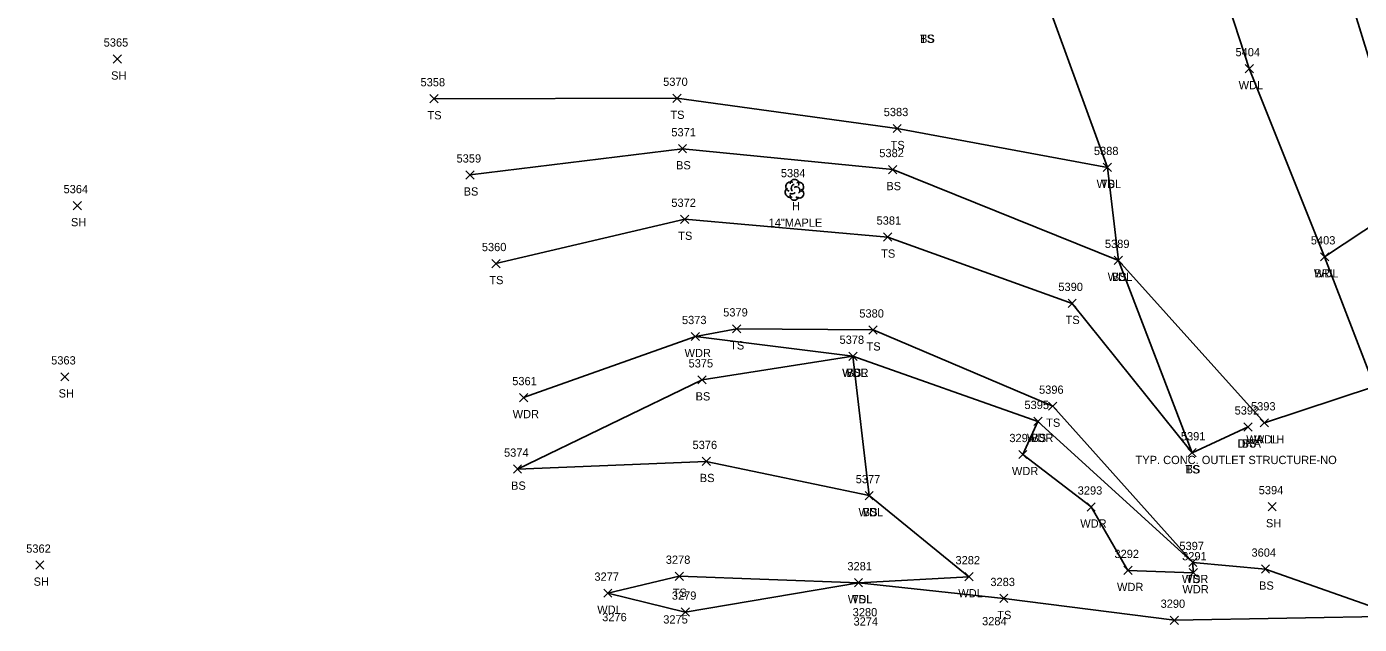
# Model space of a CAD drawing. Extents: x 1601151 to 1602912, y 499508 to 501770.
# Drawn here: x 1601159.4 to 1601482.2, y 500809.5 to 500954.3 of the extents above; entities that cross this region are included whole.
import ezdxf

# ---------------------------------------------------------------- set-up
doc = ezdxf.new("R2010")
doc.units = 0
for name, color, linetype in [('D_A', 7, 'Continuous'), ('D_C', 7, 'Continuous'), ('D_I', 7, 'Continuous'), ('D_TIC', 7, 'Continuous'), ('L_A', 7, 'Continuous'), ('L_C', 7, 'Continuous'), ('L_I', 7, 'Continuous'), ('L_TIC', 7, 'Continuous'), ('LABL', 7, 'Continuous'), ('LAWA', 7, 'Continuous'), ('LELB', 7, 'Continuous'), ('LTD', 7, 'Continuous'), ('UCO', 7, 'Continuous')]:
    doc.layers.add(name, color=color, linetype=linetype)

msp = doc.modelspace()

# ---------------------------------------------------------------- linework, layer by layer
at = {"layer": 'D_TIC'}
for points in [[(1601458.19, 500857.34), (1601460.19, 500859.34)], [(1601460.19, 500857.34), (1601458.19, 500859.34)], [(1601454.22, 500856.34), (1601456.22, 500858.34)], [(1601456.22, 500856.34), (1601454.22, 500858.34)]]:
    msp.add_lwpolyline(points, dxfattribs=at)
at = {"layer": 'L_TIC'}
for points in [[(1601180.37, 500945.47), (1601182.37, 500947.47)], [(1601182.37, 500945.47), (1601180.37, 500947.47)], [(1601454.52, 500943.14), (1601456.52, 500945.14)], [(1601456.52, 500943.14), (1601454.52, 500945.14)], [(1601257.06, 500935.85), (1601259.06, 500937.85)], [(1601259.06, 500935.85), (1601257.06, 500937.85)], [(1601315.91, 500935.96), (1601317.91, 500937.96)], [(1601317.91, 500935.96), (1601315.91, 500937.96)], [(1601369.24, 500928.63), (1601371.24, 500930.63)], [(1601371.24, 500928.63), (1601369.24, 500930.63)], [(1601317.24, 500923.73), (1601319.24, 500925.73)], [(1601319.24, 500923.73), (1601317.24, 500925.73)], [(1601368.17, 500918.69), (1601370.17, 500920.69)], [(1601370.17, 500918.69), (1601368.17, 500920.69)], [(1601420.14, 500919.2), (1601422.14, 500921.2)], [(1601422.14, 500919.2), (1601420.14, 500921.2)], [(1601420.14, 500919.2), (1601422.14, 500921.2)], [(1601422.14, 500919.2), (1601420.14, 500921.2)], [(1601265.79, 500917.38), (1601267.79, 500919.38)], [(1601267.79, 500917.38), (1601265.79, 500919.38)], [(1601170.65, 500909.95), (1601172.65, 500911.95)], [(1601172.65, 500909.95), (1601170.65, 500911.95)], [(1601317.8, 500906.65), (1601319.8, 500908.65)], [(1601319.8, 500906.65), (1601317.8, 500908.65)], [(1601366.94, 500902.34), (1601368.94, 500904.34)], [(1601368.94, 500902.34), (1601366.94, 500904.34)], [(1601272.05, 500895.92), (1601274.05, 500897.92)], [(1601274.05, 500895.92), (1601272.05, 500897.92)], [(1601422.82, 500896.69), (1601424.82, 500898.69)], [(1601424.82, 500896.69), (1601422.82, 500898.69)], [(1601422.82, 500896.69), (1601424.82, 500898.69)], [(1601424.82, 500896.69), (1601422.82, 500898.69)], [(1601472.76, 500897.55), (1601474.76, 500899.55)], [(1601474.76, 500897.55), (1601472.76, 500899.55)], [(1601472.76, 500897.55), (1601474.76, 500899.55)], [(1601474.76, 500897.55), (1601472.76, 500899.55)], [(1601411.62, 500886.27), (1601413.62, 500888.27)], [(1601413.62, 500886.27), (1601411.62, 500888.27)], [(1601330.37, 500880.1), (1601332.37, 500882.1)], [(1601332.37, 500880.1), (1601330.37, 500882.1)], [(1601363.41, 500879.84), (1601365.41, 500881.84)], [(1601365.41, 500879.84), (1601363.41, 500881.84)], [(1601320.37, 500878.25), (1601322.37, 500880.25)], [(1601322.37, 500878.25), (1601320.37, 500880.25)], [(1601358.53, 500873.47), (1601360.53, 500875.47)], [(1601360.53, 500873.47), (1601358.53, 500875.47)], [(1601358.53, 500873.47), (1601360.53, 500875.47)], [(1601360.53, 500873.47), (1601358.53, 500875.47)], [(1601358.53, 500873.47), (1601360.53, 500875.47)], [(1601360.53, 500873.47), (1601358.53, 500875.47)], [(1601167.65, 500868.47), (1601169.65, 500870.47)], [(1601169.65, 500868.47), (1601167.65, 500870.47)], [(1601321.97, 500867.75), (1601323.97, 500869.75)], [(1601323.97, 500867.75), (1601321.97, 500869.75)], [(1601278.75, 500863.45), (1601280.75, 500865.45)], [(1601280.75, 500863.45), (1601278.75, 500865.45)], [(1601406.92, 500861.37), (1601408.92, 500863.37)], [(1601408.92, 500861.37), (1601406.92, 500863.37)], [(1601403.32, 500857.67), (1601405.32, 500859.67)], [(1601405.32, 500857.67), (1601403.32, 500859.67)], [(1601403.32, 500857.67), (1601405.32, 500859.67)], [(1601405.32, 500857.67), (1601403.32, 500859.67)], [(1601458.19, 500857.34), (1601460.19, 500859.34)], [(1601460.19, 500857.34), (1601458.19, 500859.34)], [(1601454.22, 500856.34), (1601456.22, 500858.34)], [(1601456.22, 500856.34), (1601454.22, 500858.34)], [(1601322.99, 500847.98), (1601324.99, 500849.98)], [(1601324.99, 500847.98), (1601322.99, 500849.98)], [(1601399.67, 500849.66), (1601401.67, 500851.66)], [(1601401.67, 500849.66), (1601399.67, 500851.66)], [(1601440.65, 500850.08), (1601442.65, 500852.08)], [(1601442.65, 500850.08), (1601440.65, 500852.08)], [(1601440.65, 500850.08), (1601442.65, 500852.08)], [(1601442.65, 500850.08), (1601440.65, 500852.08)], [(1601277.28, 500846.12), (1601279.28, 500848.12)], [(1601279.28, 500846.12), (1601277.28, 500848.12)], [(1601277.28, 500846.12), (1601279.28, 500848.12)], [(1601279.28, 500846.12), (1601277.28, 500848.12)], [(1601362.46, 500839.7), (1601364.46, 500841.7)], [(1601364.46, 500839.7), (1601362.46, 500841.7)], [(1601362.46, 500839.7), (1601364.46, 500841.7)], [(1601364.46, 500839.7), (1601362.46, 500841.7)], [(1601416.22, 500836.95), (1601418.22, 500838.95)], [(1601418.22, 500836.95), (1601416.22, 500838.95)], [(1601460.06, 500837.03), (1601462.06, 500839.03)], [(1601462.06, 500837.03), (1601460.06, 500839.03)], [(1601161.6, 500822.87), (1601163.6, 500824.87)], [(1601163.6, 500822.87), (1601161.6, 500824.87)], [(1601425.12, 500821.58), (1601427.12, 500823.58)], [(1601427.12, 500821.58), (1601425.12, 500823.58)], [(1601440.85, 500823.51), (1601442.85, 500825.51)], [(1601442.85, 500823.51), (1601440.85, 500825.51)], [(1601440.85, 500823.51), (1601442.85, 500825.51)], [(1601442.85, 500823.51), (1601440.85, 500825.51)], [(1601458.44, 500821.91), (1601460.44, 500823.91)], [(1601460.44, 500821.91), (1601458.44, 500823.91)], [(1601316.46, 500820.18), (1601318.46, 500822.18)], [(1601318.46, 500820.18), (1601316.46, 500822.18)], [(1601359.87, 500818.6), (1601361.87, 500820.6)], [(1601361.87, 500818.6), (1601359.87, 500820.6)], [(1601359.87, 500818.6), (1601361.87, 500820.6)], [(1601361.87, 500818.6), (1601359.87, 500820.6)], [(1601386.62, 500820.06), (1601388.62, 500822.06)], [(1601388.62, 500820.06), (1601386.62, 500822.06)], [(1601440.94, 500821.03), (1601442.94, 500823.03)], [(1601442.94, 500821.03), (1601440.94, 500823.03)], [(1601299.17, 500816.08), (1601301.17, 500818.08)], [(1601301.17, 500816.08), (1601299.17, 500818.08)], [(1601395.07, 500814.79), (1601397.07, 500816.79)], [(1601397.07, 500814.79), (1601395.07, 500816.79)], [(1601317.92, 500811.49), (1601319.92, 500813.49)], [(1601319.92, 500811.49), (1601317.92, 500813.49)], [(1601436.39, 500809.52), (1601438.39, 500811.52)], [(1601438.39, 500809.52), (1601436.39, 500811.52)]]:
    msp.add_lwpolyline(points, dxfattribs=at)
at = {"layer": 'LABL'}
msp.add_lwpolyline([(1601473.76, 500898.55), (1601497.29, 500914.1)], dxfattribs=at)
at = {"layer": 'LAWA'}
for points in [[(1601259.73, 501080.04), (1601281.1, 501061.19), (1601290.64, 501054.14), (1601330.77, 501022.9), (1601342.69, 501019.91), (1601398.12, 501006.17), (1601406.51, 500960.5), (1601421.14, 500920.2), (1601423.82, 500897.69), (1601459.19, 500858.34), (1601485.88, 500867.15), (1601473.76, 500898.55), (1601455.52, 500944.14), (1601437.51, 500999.51), (1601438.3, 501031.99)], [(1601279.75, 500864.45), (1601321.37, 500879.25), (1601359.53, 500874.47)], [(1601300.17, 500817.08), (1601318.92, 500812.49), (1601360.87, 500819.6), (1601387.62, 500821.06), (1601363.46, 500840.7), (1601359.53, 500874.47)], [(1601441.94, 500822.03), (1601426.12, 500822.58), (1601417.22, 500837.95), (1601400.67, 500850.66), (1601404.32, 500858.67), (1601441.85, 500824.51), (1601441.94, 500822.03)]]:
    msp.add_lwpolyline(points, dxfattribs=at)
at = {"layer": 'LELB'}
for points in [[(1601258.06, 500936.85), (1601316.91, 500936.96), (1601370.24, 500929.63), (1601421.14, 500920.2)], [(1601266.79, 500918.38), (1601318.24, 500924.73), (1601369.17, 500919.69), (1601423.82, 500897.69), (1601441.65, 500851.08), (1601455.22, 500857.34)], [(1601273.05, 500896.92), (1601318.8, 500907.65), (1601367.94, 500903.34), (1601412.62, 500887.27), (1601441.65, 500851.08)], [(1601321.37, 500879.25), (1601331.37, 500881.1)], [(1601331.37, 500881.1), (1601364.41, 500880.84), (1601407.92, 500862.37), (1601441.85, 500824.51)], [(1601278.28, 500847.12), (1601322.97, 500868.75), (1601359.53, 500874.47), (1601404.32, 500858.67)], [(1601278.28, 500847.12), (1601323.99, 500848.98), (1601363.46, 500840.7)], [(1601459.44, 500822.91), (1601441.85, 500824.51)], [(1601317.46, 500821.18), (1601300.17, 500817.08)], [(1601317.46, 500821.18), (1601360.87, 500819.6), (1601396.07, 500815.79), (1601437.39, 500810.52), (1601491.8, 500811.5), (1601526.7, 500809.42), (1601537.19, 500807.51), (1601550.66, 500808.84), (1601565.73, 500796.87), (1601596.61, 500795.52)], [(1601491.8, 500811.5), (1601459.44, 500822.91)]]:
    msp.add_lwpolyline(points, dxfattribs=at)
at = {"layer": 'LTD'}
msp.add_line((1601345.33, 500914.83), (1601345.33, 500914.83), dxfattribs=at)
msp.add_line((1601345.33, 500914.83), (1601345.33, 500914.83), dxfattribs=at)
msp.add_arc((1601345.38, 500916.27), 1.05, 335.5272, 180.9563, dxfattribs=at)
for centre, major_axis, ratio, start_param, end_param in [((1601344.54, 500915.5), (1.21, -0.51), 0.895232, 1.570796, 4.712389), ((1601344.25, 500914.12), (0.58, -1.04), 0.959034, 3.141593, 6.283185), ((1601344.87, 500914.08), (-0.625, -0.083), 0.423636, 0, 3.141593), ((1601345.12, 500915.29), (-0.208, -0.792), 0.645439, 3.141593, 6.283185), ((1601345.83, 500914.67), (-0.5, 0.667), 0.989748, 3.141593, 6.283185), ((1601346.33, 500914), (-1.09, 0.79), 0.841452, 1.570796, 4.712389), ((1601346.37, 500915.42), (-1.14, -0.48), 0.949671, 1.570796, 4.712389), ((1601345.33, 500913.33), (0.26, 1.06), 0.942809, 1.570796, 4.712389)]:
    msp.add_ellipse(centre, major_axis=major_axis, ratio=ratio, start_param=start_param, end_param=end_param, dxfattribs=at)
at = {"layer": 'UCO'}
msp.add_lwpolyline([(1601766.65, 501489.44), (1601471.02, 501503.9), (1601438.7, 501339.97), (1601411.28, 501184.01), (1601489.93, 500928.89)], dxfattribs=at)

# ---------------------------------------------------------------- texts
at = {"layer": 'D_A'}
for s, p in [('DRA', (1601452.68, 500852.34)), ('WALLH', (1601454.78, 500853.34))]:
    msp.add_text(s, height=2, dxfattribs=at).set_placement(p)
at = {"layer": 'D_C'}
msp.add_text('TYP. CONC. OUTLET STRUCTURE-NO ', height=2, dxfattribs=at).set_placement((1601427.97, 500848.34))
at = {"layer": 'D_I'}
for s, p in [('5392', (1601451.96, 500860.34)), ('5393', (1601455.93, 500861.34))]:
    msp.add_text(s, height=2, dxfattribs=at).set_placement(p)
at = {"layer": 'L_A'}
for s, p in [('TS', (1601375.76, 500950.38)), ('BS', (1601375.79, 500950.38)), ('SH', (1601179.86, 500941.47)), ('WDL', (1601452.94, 500939.14)), ('TS', (1601256.47, 500931.85)), ('TS', (1601315.31, 500931.96)), ('TS', (1601368.65, 500924.63)), ('BS', (1601316.68, 500919.73)), ('WDL', (1601418.55, 500915.2)), ('TS', (1601419.55, 500915.2)), ('BS', (1601265.23, 500913.38)), ('BS', (1601367.61, 500914.69)), ('H', (1601344.76, 500909.83)), ('SH', (1601170.13, 500905.95)), ('TS', (1601317.21, 500902.65)), ('TS', (1601366.35, 500898.34)), ('WDL', (1601421.23, 500892.69)), ('BS', (1601422.26, 500892.69)), ('WDL', (1601471.17, 500893.55)), ('BRL', (1601471.3, 500893.55)), ('TS', (1601271.46, 500891.92)), ('TS', (1601411.03, 500882.27)), ('TS', (1601329.78, 500876.1)), ('WDR', (1601318.74, 500874.25)), ('TS', (1601362.82, 500875.84)), ('WDR', (1601356.9, 500869.47)), ('WDL', (1601356.95, 500869.47)), ('BS', (1601357.98, 500869.47)), ('SH', (1601167.14, 500864.47)), ('BS', (1601321.41, 500863.75)), ('WDR', (1601277.11, 500859.45)), ('TS', (1601406.33, 500857.37)), ('WDR', (1601401.68, 500853.67)), ('BS', (1601402.76, 500853.67)), ('BS', (1601453.66, 500852.34)), ('WDL', (1601456.61, 500853.34)), ('BS', (1601322.43, 500843.98)), ('WDR', (1601398.03, 500845.66)), ('TS', (1601440.06, 500846.08)), ('BS', (1601440.09, 500846.08)), ('BS', (1601276.72, 500842.12)), ('BS', (1601276.72, 500842.12)), ('WDL', (1601360.88, 500835.7)), ('BS', (1601361.9, 500835.7)), ('WDR', (1601414.58, 500832.95)), ('SH', (1601459.55, 500833.03)), ('SH', (1601161.09, 500818.87)), ('WDR', (1601439.21, 500819.51)), ('TS', (1601440.26, 500819.51)), ('TS', (1601315.87, 500816.18)), ('WDL', (1601385.03, 500816.06)), ('WDR', (1601423.48, 500817.58)), ('WDR', (1601439.31, 500817.03)), ('BS', (1601457.88, 500817.91)), ('WDL', (1601297.59, 500812.08)), ('WDL', (1601358.29, 500814.6)), ('TS', (1601359.28, 500814.6)), ('TS', (1601394.48, 500810.79))]:
    msp.add_text(s, height=2, dxfattribs=at).set_placement(p)
at = {"layer": 'L_C'}
msp.add_text('14"MAPLE', height=2, dxfattribs=at).set_placement((1601339.11, 500905.83))
at = {"layer": 'L_I'}
for s, p in [('5365', (1601178.06, 500949.47)), ('5404', (1601452.18, 500947.14)), ('5358', (1601254.8, 500939.85)), ('5370', (1601313.56, 500939.96)), ('5383', (1601366.98, 500932.63)), ('5371', (1601315.54, 500927.73)), ('5359', (1601263.52, 500921.38)), ('5382', (1601365.91, 500922.69)), ('5388', (1601417.88, 500923.2)), ('5388', (1601417.88, 500923.2)), ('5384', (1601342.07, 500917.83)), ('5364', (1601168.34, 500913.95)), ('5372', (1601315.54, 500910.65)), ('5381', (1601365.25, 500906.34)), ('5360', (1601269.65, 500899.92)), ('5389', (1601420.55, 500900.69)), ('5389', (1601420.55, 500900.69)), ('5403', (1601470.42, 500901.55)), ('5403', (1601470.42, 500901.55)), ('5390', (1601409.28, 500890.27)), ('5379', (1601328.1, 500884.1)), ('5380', (1601361.07, 500883.84)), ('5373', (1601318.11, 500882.25)), ('5378', (1601356.28, 500877.47)), ('5378', (1601356.28, 500877.47)), ('5378', (1601356.28, 500877.47)), ('5363', (1601165.34, 500872.47)), ('5375', (1601319.71, 500871.75)), ('5361', (1601277.01, 500867.45)), ('5396', (1601404.6, 500865.37)), ('5395', (1601401.06, 500861.67)), ('5395', (1601401.06, 500861.67)), ('5392', (1601451.96, 500860.34)), ('5393', (1601455.93, 500861.34)), ('3294', (1601397.41, 500853.66)), ('5391', (1601438.95, 500854.08)), ('5391', (1601438.95, 500854.08)), ('5376', (1601320.68, 500851.98)), ('5374', (1601275.02, 500850.12)), ('5374', (1601275.02, 500850.12)), ('5377', (1601360.2, 500843.7)), ('5377', (1601360.2, 500843.7)), ('3293', (1601413.96, 500840.95)), ('5394', (1601457.8, 500841.03)), ('5362', (1601159.3, 500826.87)), ('3292', (1601422.86, 500825.58)), ('5397', (1601438.59, 500827.51)), ('5397', (1601438.59, 500827.51)), ('3291', (1601439.25, 500825.03)), ('3604', (1601456.05, 500825.91)), ('3278', (1601314.2, 500824.18)), ('3281', (1601358.18, 500822.6)), ('3281', (1601358.18, 500822.6)), ('3282', (1601384.36, 500824.06)), ('3277', (1601296.91, 500820.08)), ('3283', (1601392.81, 500818.79)), ('3279', (1601315.66, 500815.49)), ('3290', (1601434.04, 500813.52)), ('3276', (1601298.79, 500810.28)), ('3275', (1601313.58, 500809.72)), ('3275', (1601313.58, 500809.72)), ('3280', (1601359.46, 500811.47)), ('3274', (1601359.67, 500809.22)), ('3284', (1601390.8, 500809.3))]:
    msp.add_text(s, height=2, dxfattribs=at).set_placement(p)

doc.saveas('drawing.dxf')
